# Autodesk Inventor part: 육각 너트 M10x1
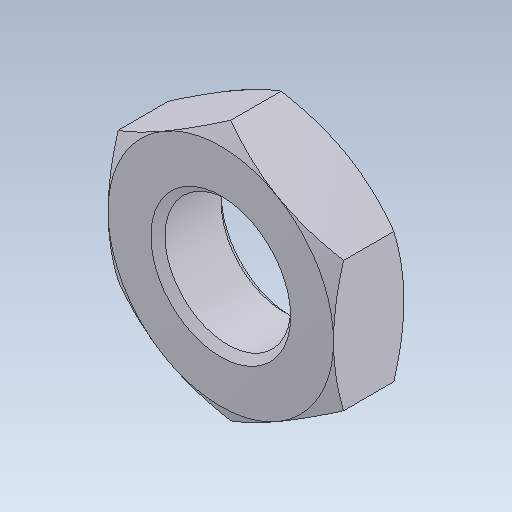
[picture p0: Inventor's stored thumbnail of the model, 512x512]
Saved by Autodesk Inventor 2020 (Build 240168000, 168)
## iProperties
Created: 2024-04
Part Number: 육각 너트 M10x1
Material: 강철, 연강
Description: 6각 가는 너트 - 이중 모따기(부품 등급 A) - 정밀 나사산
Document SubType Name: Modeling
Designer: oem
Density: 7.85 g/cm^3
Appearance: 기본값
Mass: 6.12359 g
Surface Area: 6.99154 cm^2
Volume: 0.780075 cm^3
Sending System: Autodesk Inventor 2025
Preprocessor: ST-DEVELOPER v20
Author: jhkim
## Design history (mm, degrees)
feature "Solid1"
node "솔리드1"
